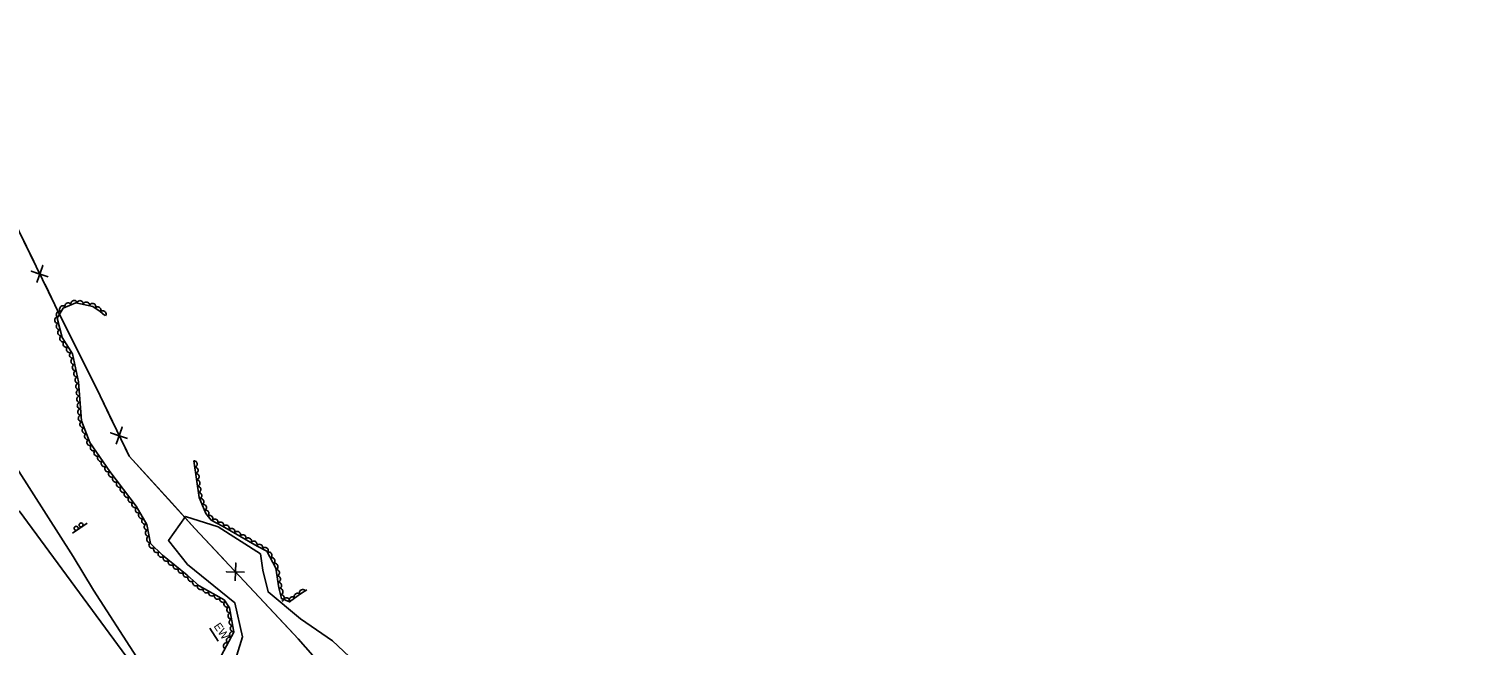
# Model space of a CAD drawing. Extents: x 1746719 to 1766531, y 631721 to 662391.
# Drawn here: x 1764475 to 1765372, y 633323 to 633708 of the extents above; entities that cross this region are included whole.
import ezdxf

# ---------------------------------------------------------------- set-up
doc = ezdxf.new("R2010")
doc.units = 0
for name, color, linetype in [('SURVEY - AERIAL SURVEY - Photo Control - Points - Elevations', 7, 'Continuous'), ('SURVEY - AERIAL SURVEY - Photo Control - Points - Locators', 7, 'Continuous'), ('SURVEY - AERIAL SURVEY - Photo Control with Text', 7, 'Continuous'), ('SURVEY - CENTERLINE - Existing Roads Curve Text', 7, 'Continuous'), ('SURVEY - CENTERLINE - Existing Roads Text', 7, 'Continuous'), ('SURVEY - CENTERLINE - Preliminary - Development', 7, 'Continuous'), ('SURVEY - CONTROL - Grid', 7, 'Continuous')]:
    doc.layers.add(name, color=color, linetype=linetype)

msp = doc.modelspace()

# ---------------------------------------------------------------- linework, layer by layer
at = {"layer": 'SURVEY - AERIAL SURVEY - Photo Control - Points - Elevations'}
for points in [[(1764460.26, 633445.38), (1764503.08, 633378.08)], [(1764563.3, 633279.03), (1764469.51, 633406.68)], [(1765405.55, 632796.71), (1765330.18, 632801.39), (1765276.68, 632810.4), (1765227.62, 632820.45), (1765175.33, 632835.88), (1765105.4, 632862.94), (1765045.31, 632890.6), (1764952.52, 632941.27), (1764893.1, 632976.98), (1764852.73, 633007.31), (1764794.71, 633051.44), (1764731.05, 633102.95), (1764684.95, 633147.06), (1764630.12, 633206.72), (1764589.37, 633257.76), (1764542.78, 633315.43), (1764515.94, 633356.98), (1764503.08, 633378.08)]]:
    msp.add_lwpolyline(points, dxfattribs=at)
at = {"layer": 'SURVEY - AERIAL SURVEY - Photo Control - Points - Locators'}
msp.add_lwpolyline([(1764602.79, 633307.64), (1764608.92, 633327.98), (1764604.08, 633349.24), (1764574.6, 633373.1), (1764562.74, 633388.1), (1764573.45, 633403.17), (1764593.66, 633396.69), (1764620.25, 633379.72), (1764621.76, 633369.54), (1764624.91, 633355.98), (1764645.19, 633339.04), (1764665.13, 633325.29), (1764686.24, 633305.64)], dxfattribs=at)
at = {"layer": 'SURVEY - AERIAL SURVEY - Photo Control with Text'}
for points in [[(1764595.81, 633316.48), (1764603.61, 633330.78), (1764602.39, 633337.91), (1764600.86, 633345.96), (1764597.46, 633350.94), (1764581.79, 633359.82), (1764574.49, 633366.51), (1764558.96, 633378.91), (1764551.51, 633386.18), (1764549.15, 633398.14), (1764542.59, 633409.49), (1764526.05, 633431.14), (1764513.6, 633449.36), (1764508.39, 633462.89), (1764506.47, 633487.32), (1764502.67, 633504.64), (1764496.29, 633514.88), (1764493.19, 633527.06), (1764496.91, 633533.32), (1764504.83, 633536.7), (1764515.56, 633534.28), (1764519.99, 633531.19), (1764523.02, 633528.67)], [(1764578.52, 633437.9), (1764581.79, 633414.97), (1764586.14, 633404.96), (1764589.33, 633400.87), (1764596.55, 633397.06), (1764618.19, 633384.62), (1764624.11, 633381.35), (1764629.68, 633370.89), (1764631.73, 633358.6), (1764633.25, 633351.81), (1764638.28, 633349.68), (1764645.18, 633354.66), (1764649.04, 633357.3), (1764649.14, 633357.35)]]:
    msp.add_lwpolyline(points, dxfattribs=at)
for centre, major_axis in [((1764503.69, 633536.21), (1.84, 0.79)), ((1764507.53, 633536.09), (1.95, -0.44)), ((1764494.55, 633529.34), (1.02, 1.72)), ((1764496.59, 633532.78), (1.02, 1.72)), ((1764500.02, 633534.64), (1.84, 0.79)), ((1764511.43, 633535.21), (1.95, -0.44)), ((1764515.33, 633534.33), (1.95, -0.44)), ((1764518.65, 633532.12), (1.64, -1.14)), ((1764521.81, 633529.68), (1.54, -1.28)), ((1764493.52, 633525.76), (-0.49, 1.94)), ((1764494.51, 633521.88), (-0.49, 1.94)), ((1764495.5, 633518), (-0.49, 1.94)), ((1764496.7, 633514.22), (-1.06, 1.7)), ((1764498.82, 633510.82), (-1.06, 1.7)), ((1764500.93, 633507.43), (-1.06, 1.7)), ((1764502.82, 633503.94), (-0.43, 1.95)), ((1764503.68, 633500.04), (-0.43, 1.95)), ((1764504.54, 633496.13), (-0.43, 1.95)), ((1764505.4, 633492.22), (-0.43, 1.95)), ((1764506.26, 633488.32), (-0.43, 1.95)), ((1764506.71, 633484.35), (-0.16, 1.99)), ((1764507.02, 633480.36), (-0.16, 1.99)), ((1764507.33, 633476.37), (-0.16, 1.99)), ((1764507.65, 633472.39), (-0.16, 1.99)), ((1764507.96, 633468.4), (-0.16, 1.99)), ((1764508.27, 633464.41), (-0.16, 1.99)), ((1764509.28, 633460.58), (-0.72, 1.87)), ((1764510.72, 633456.85), (-0.72, 1.87)), ((1764512.16, 633453.11), (-0.72, 1.87)), ((1764513.6, 633449.38), (-0.72, 1.87)), ((1764515.85, 633446.08), (-1.13, 1.65)), ((1764518.1, 633442.77), (-1.13, 1.65)), ((1764520.36, 633439.47), (-1.13, 1.65)), ((1764522.61, 633436.17), (-1.13, 1.65)), ((1764524.87, 633432.86), (-1.13, 1.65)), ((1764527.21, 633429.62), (-1.21, 1.59)), ((1764578.8, 633435.92), (0.28, -1.98)), ((1764579.36, 633431.96), (0.28, -1.98)), ((1764529.64, 633426.44), (-1.21, 1.59)), ((1764532.07, 633423.26), (-1.21, 1.59)), ((1764534.5, 633420.09), (-1.21, 1.59)), ((1764579.93, 633428), (0.28, -1.98)), ((1764580.5, 633424.04), (0.28, -1.98)), ((1764581.06, 633420.08), (0.28, -1.98)), ((1764536.92, 633416.91), (-1.21, 1.59)), ((1764539.35, 633413.73), (-1.21, 1.59)), ((1764581.63, 633416.12), (0.28, -1.98)), ((1764582.92, 633412.36), (0.8, -1.83)), ((1764541.78, 633410.55), (-1.21, 1.59)), ((1764543.93, 633407.18), (-1, 1.73)), ((1764545.93, 633403.72), (-1, 1.73)), ((1764584.51, 633408.7), (0.8, -1.83)), ((1764586.11, 633405.03), (0.8, -1.83)), ((1764588.55, 633401.86), (1.23, -1.58)), ((1764547.93, 633400.26), (-1, 1.73)), ((1764549.45, 633396.62), (-0.39, 1.96)), ((1764550.23, 633392.69), (-0.39, 1.96)), ((1764591.75, 633399.59), (1.77, -0.93)), ((1764595.29, 633397.72), (1.77, -0.93)), ((1764598.78, 633395.78), (1.73, -1)), ((1764602.25, 633393.78), (1.73, -1)), ((1764551, 633388.77), (-0.39, 1.96)), ((1764552.49, 633385.23), (-1.43, 1.4)), ((1764605.72, 633391.79), (1.73, -1)), ((1764609.18, 633389.8), (1.73, -1)), ((1764612.65, 633387.8), (1.73, -1)), ((1764616.12, 633385.81), (1.73, -1)), ((1764619.6, 633383.84), (1.75, -0.97)), ((1764555.35, 633382.43), (-1.43, 1.4)), ((1764558.21, 633379.64), (-1.43, 1.4)), ((1764561.27, 633377.07), (-1.56, 1.25)), ((1764623.1, 633381.91), (1.75, -0.97)), ((1764625.45, 633378.84), (0.94, -1.77)), ((1764627.33, 633375.31), (0.94, -1.77)), ((1764564.4, 633374.57), (-1.56, 1.25)), ((1764567.52, 633372.08), (-1.56, 1.25)), ((1764570.65, 633369.58), (-1.56, 1.25)), ((1764573.77, 633367.08), (-1.56, 1.25)), ((1764629.21, 633371.78), (0.94, -1.77)), ((1764630.18, 633367.93), (0.33, -1.97)), ((1764576.76, 633364.43), (-1.47, 1.35)), ((1764579.71, 633361.72), (-1.47, 1.35)), ((1764582.81, 633359.24), (-1.74, 0.99)), ((1764630.83, 633363.99), (0.33, -1.97)), ((1764631.49, 633360.04), (0.33, -1.97)), ((1764586.29, 633357.26), (-1.74, 0.99)), ((1764589.78, 633355.29), (-1.74, 0.99)), ((1764593.26, 633353.32), (-1.74, 0.99)), ((1764596.74, 633351.35), (-1.74, 0.99)), ((1764599.25, 633348.32), (-1.13, 1.65)), ((1764632.29, 633356.12), (0.44, -1.95)), ((1764633.16, 633352.22), (0.44, -1.95)), ((1764636.55, 633350.41), (1.84, -0.78)), ((1764640, 633350.92), (1.62, 1.17)), ((1764643.24, 633353.26), (1.62, 1.17)), ((1764646.51, 633355.57), (1.65, 1.13)), ((1764601.07, 633344.84), (-0.37, 1.96)), ((1764601.82, 633340.91), (-0.37, 1.96)), ((1764602.55, 633336.98), (-0.34, 1.97)), ((1764603.23, 633333.04), (-0.34, 1.97)), ((1764598.96, 633322.26), (0.96, 1.76)), ((1764600.88, 633325.77), (0.96, 1.76)), ((1764602.79, 633329.28), (0.96, 1.76))]:
    msp.add_ellipse(centre, major_axis=major_axis, ratio=0.940188, start_param=0, end_param=3.141593, dxfattribs=at)
at = {"layer": 'SURVEY - CENTERLINE - Existing Roads Curve Text'}
for points in [[(1764406.17, 633707.92), (1764432.28, 633655.64), (1764464.74, 633591.06), (1764491.8, 633535.35), (1764519.98, 633478.51), (1764538.21, 633440.74), (1764579.23, 633395.69), (1764609.99, 633362.72), (1764643.83, 633326.65), (1764668, 633298.93)], [(1764456.56, 633607.34), (1764464.74, 633591.06), (1764478.63, 633562.47)], [(1764487.64, 633552.84), (1764476.99, 633556.45), (1764482.34, 633554.6), (1764484.19, 633559.95), (1764480.45, 633549.35)], [(1764485.66, 633547.99), (1764491.8, 633535.35), (1764506.17, 633506.37)], [(1764506.17, 633506.37), (1764519.98, 633478.51), (1764528.2, 633461.48)], [(1764537.18, 633451.83), (1764526.54, 633455.47), (1764531.89, 633453.6), (1764533.75, 633458.94), (1764529.98, 633448.35)], [(1764535.19, 633446.98), (1764538.21, 633440.74), (1764564.78, 633411.56)], [(1764564.78, 633411.56), (1764579.23, 633395.69), (1764598.7, 633374.82)], [(1764610.15, 633368.27), (1764598.91, 633368.59), (1764604.56, 633368.39), (1764604.76, 633374.05), (1764604.3, 633362.81)], [(1764609.68, 633363.05), (1764609.99, 633362.72), (1764641.43, 633329.21)], [(1764641.43, 633329.21), (1764643.83, 633326.65), (1764668, 633298.93)]]:
    msp.add_lwpolyline(points, dxfattribs=at)
at = {"layer": 'SURVEY - CENTERLINE - Existing Roads Text'}
msp.add_lwpolyline([(1764588.49, 633333.31), (1764593.68, 633325.28)], dxfattribs=at)
at = {"layer": 'SURVEY - CONTROL - Grid'}
msp.add_line((1764512, 633398.96), (1764502.76, 633392.64), dxfattribs=at)
for centre in [(1764505.06, 633395.7), (1764508.16, 633397.82)]:
    msp.add_circle(centre, 1.25, dxfattribs=at)

# ---------------------------------------------------------------- texts
at = {"layer": 'SURVEY - CENTERLINE - Preliminary - Development'}
msp.add_text('EW', height=5, rotation=304.32105, dxfattribs=at).set_placement((1764590.71, 633334.55))

doc.saveas('drawing.dxf')
